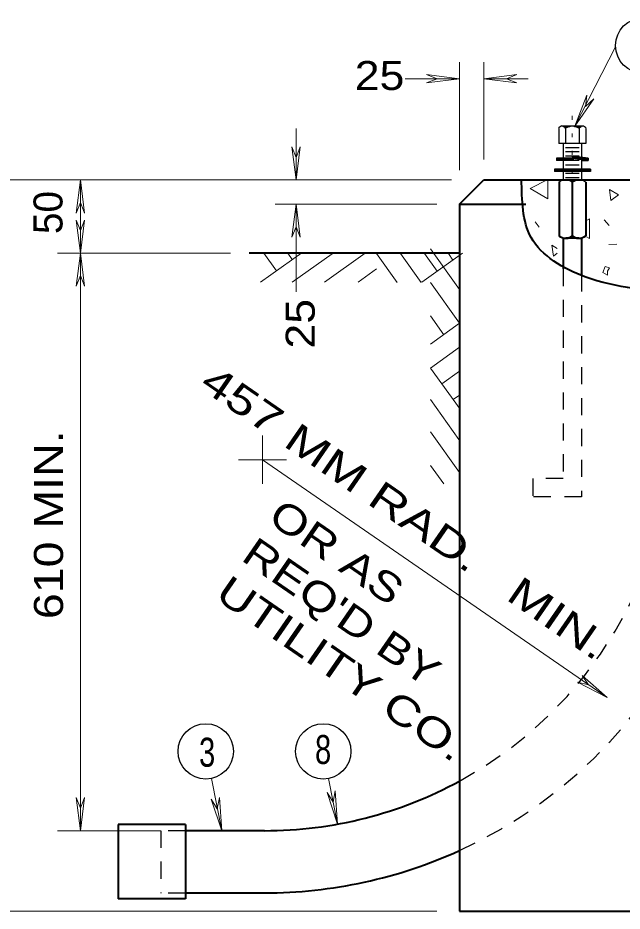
# Model space of a CAD drawing. Extents: x 312583 to 312854, y 144419 to 144597.
# Drawn here: x 312722.32 to 312738.15, y 144438.03 to 144461.45 of the extents above; entities that cross this region are included whole.
import ezdxf

# ---------------------------------------------------------------- set-up
doc = ezdxf.new("R2010")
doc.units = 0
doc.header["$LTSCALE"] = 0.3
doc.linetypes.add('DOTTED', pattern=[1.5, 0.3, -1.2])
doc.linetypes.add('SHORT_DASHED', pattern=[2.7, 1.5, -1.2])
doc.layers.add('1', color=7, linetype='Continuous', lineweight=25)
doc.layers.add('2', color=7, linetype='Continuous', lineweight=13)

msp = doc.modelspace()

# ---------------------------------------------------------------- linework, layer by layer
at = {"layer": '1', "linetype": 'DOTTED', "lineweight": 13}
msp.add_line((312736.843, 144458.8804), (312736.843, 144457.2014), dxfattribs=at)
at = {"layer": '1'}
for p, q in [((312737.1113, 144458.6044), (312736.5746, 144458.6197)), ((312736.4903, 144458.5507), (312736.4903, 144458.1597)), ((312736.6666, 144458.5507), (312736.6666, 144458.1597)), ((312737.027, 144458.5507), (312737.027, 144458.1597)), ((312737.2033, 144458.5507), (312737.2033, 144458.1597)), ((312737.2033, 144458.1597), (312736.4903, 144458.1597)), ((312736.6053, 144458.1597), (312736.6053, 144457.2014)), ((312737.0883, 144458.1597), (312737.0883, 144457.2014)), ((312737.027, 144458.0447), (312736.6666, 144458.0447)), ((312737.027, 144457.9374), (312736.6666, 144457.9374)), ((312736.429, 144457.7687), (312736.429, 144457.7074)), ((312736.866, 144457.7687), (312736.429, 144457.7687)), ((312736.8813, 144457.7074), (312736.429, 144457.7074)), ((312737.027, 144457.8224), (312736.6666, 144457.8224)), ((312737.027, 144457.7074), (312736.6666, 144457.7074)), ((312737.257, 144457.7687), (312737.257, 144457.7074)), ((312737.3183, 144457.485), (312736.3753, 144457.485)), ((312736.3753, 144457.485), (312736.3753, 144457.4237)), ((312737.3183, 144457.4697), (312736.3753, 144457.4697)), ((312737.3183, 144457.4544), (312736.3753, 144457.4544)), ((312737.3183, 144457.439), (312736.3753, 144457.439)), ((312737.027, 144457.5924), (312736.6666, 144457.5924)), ((312737.3183, 144457.485), (312737.3183, 144457.4237)), ((312737.3183, 144457.4237), (312736.3753, 144457.4237)), ((312737.0883, 144457.2014), (312736.6053, 144457.2014)), ((312737.027, 144457.37), (312736.6666, 144457.37)), ((312737.027, 144457.255), (312736.6666, 144457.255)), ((312737.0193, 144457.2014), (312736.6743, 144457.2014))]:
    msp.add_line(p, q, dxfattribs=at)
at = {"layer": '1', "lineweight": 40}
for p, q in [((312733.8913, 144456.565), (312734.5276, 144457.2014)), ((312734.5276, 144457.2014), (312777.9746, 144457.2014)), ((312736.843, 144457.2014), (312736.843, 144455.6757)), ((312736.498, 144457.14), (312736.498, 144455.737)), ((312737.1956, 144457.14), (312737.1956, 144455.737)), ((312733.8913, 144456.565), (312733.8913, 144438.0347)), ((312733.8913, 144456.565), (312735.624, 144456.565)), ((312736.6053, 144455.6757), (312736.6053, 144454.8707)), ((312737.0193, 144455.6757), (312736.6743, 144455.6757)), ((312737.0883, 144455.6757), (312737.0883, 144454.725)), ((312733.8913, 144455.2847), (312728.379, 144455.2847)), ((312726.7076, 144440.304), (312724.9443, 144440.304)), ((312724.9443, 144440.304), (312724.9443, 144438.3567)), ((312726.7076, 144440.304), (312726.7076, 144438.3567)), ((312728.7776, 144440.143), (312726.7076, 144440.143)), ((312728.7776, 144438.51), (312726.7076, 144438.51)), ((312726.7076, 144438.3567), (312724.9443, 144438.3567)), ((312733.8913, 144438.0347), (312778.611, 144438.0347))]:
    msp.add_line(p, q, dxfattribs=at)
at = {"layer": '1', "linetype": 'SHORT_DASHED'}
for p, q in [((312736.6053, 144454.8707), (312736.6053, 144449.3737)), ((312737.0883, 144454.725), (312737.0883, 144448.8984)), ((312737.0883, 144448.8984), (312735.808, 144448.8984)), ((312726.0636, 144440.143), (312726.0636, 144438.51)), ((312726.7076, 144440.143), (312726.0636, 144440.143)), ((312726.7076, 144438.51), (312726.0636, 144438.51))]:
    msp.add_line(p, q, dxfattribs=at)
at = {"layer": '1'}
for points in [[(312736.5976, 144458.612), (312736.797, 144458.612), (312736.7663, 144458.6044), (312736.7433, 144458.5967), (312736.705, 144458.5814), (312736.6666, 144458.5584), (312736.6513, 144458.5814), (312736.636, 144458.589), (312736.6053, 144458.6044), (312736.7816, 144458.6044), (312736.7356, 144458.5967), (312736.6973, 144458.5814), (312736.6666, 144458.566), (312736.6436, 144458.589), (312736.6206, 144458.6044), (312736.7586, 144458.6044), (312736.7126, 144458.589), (312736.6666, 144458.566), (312736.6283, 144458.6044), (312736.7433, 144458.6044), (312736.6666, 144458.5737), (312736.636, 144458.5967), (312736.7356, 144458.6044), (312736.6666, 144458.5737), (312736.6436, 144458.5967), (312736.7203, 144458.5967), (312736.6666, 144458.5814), (312736.6513, 144458.5967), (312736.6973, 144458.5967), (312736.6666, 144458.5814), (312736.659, 144458.5967), (312736.682, 144458.589), (312736.6666, 144458.589)], [(312737.0883, 144458.612), (312736.889, 144458.612), (312736.9273, 144458.6044), (312736.9503, 144458.5967), (312736.9886, 144458.5814), (312737.027, 144458.5584), (312737.0346, 144458.5814), (312737.0576, 144458.589), (312737.0806, 144458.6044), (312736.9043, 144458.6044), (312736.958, 144458.5967), (312736.9963, 144458.5814), (312737.0193, 144458.566), (312737.05, 144458.589), (312737.073, 144458.6044), (312736.9273, 144458.6044), (312736.981, 144458.589), (312737.0193, 144458.566), (312737.0576, 144458.6044), (312736.9426, 144458.6044), (312737.027, 144458.5737), (312737.0576, 144458.5967), (312736.958, 144458.6044), (312737.027, 144458.5737), (312737.05, 144458.5967), (312736.9733, 144458.5967), (312737.027, 144458.5814), (312737.0346, 144458.5967), (312736.9886, 144458.5967), (312737.0193, 144458.5814), (312737.027, 144458.5967), (312737.0116, 144458.589), (312737.0193, 144458.589)], [(312736.8736, 144457.715), (312736.4366, 144457.715), (312736.4366, 144457.761), (312736.8583, 144457.7534), (312736.8736, 144457.7227), (312736.4443, 144457.7227), (312736.4443, 144457.7534), (312736.8506, 144457.7457), (312736.8583, 144457.7304), (312736.452, 144457.7304), (312736.4596, 144457.738), (312736.4596, 144457.7457), (312736.8506, 144457.7457), (312736.8506, 144457.738), (312736.4596, 144457.738)], [(312737.257, 144457.7687), (312736.843, 144457.8224), (312736.8813, 144457.7074)], [(312737.0883, 144457.7074), (312737.257, 144457.715), (312737.2493, 144457.761), (312736.8583, 144457.8147), (312736.8736, 144457.7687), (312737.0883, 144457.738), (312737.0883, 144457.715), (312737.2493, 144457.7227), (312737.2493, 144457.7534), (312736.866, 144457.807), (312736.8736, 144457.7764), (312737.096, 144457.738), (312737.1036, 144457.7227), (312737.2416, 144457.7304), (312737.2416, 144457.7457), (312736.8813, 144457.7994), (312736.8813, 144457.784), (312737.096, 144457.7457), (312737.1113, 144457.738), (312737.1496, 144457.7304), (312737.234, 144457.738), (312736.889, 144457.7917), (312737.1803, 144457.738)], [(312736.866, 144457.7687), (312737.257, 144457.7074), (312737.0883, 144457.7074)], [(312736.9733, 144457.2014), (312736.7126, 144457.2014), (312736.7433, 144457.1937), (312736.774, 144457.186), (312736.8046, 144457.1707), (312736.82, 144457.163), (312736.843, 144457.1477), (312736.843, 144457.14), (312736.8966, 144457.1707), (312736.935, 144457.1937), (312736.958, 144457.1937), (312736.7356, 144457.2014), (312736.751, 144457.1937), (312736.774, 144457.1937), (312736.797, 144457.1784), (312736.8276, 144457.163), (312736.8353, 144457.1554), (312736.843, 144457.1477), (312736.889, 144457.1784), (312736.935, 144457.1937), (312736.7663, 144457.1937), (312736.8046, 144457.1784), (312736.843, 144457.1554), (312736.9196, 144457.1937), (312736.7816, 144457.1937), (312736.843, 144457.1554), (312736.9043, 144457.186), (312736.797, 144457.1937), (312736.843, 144457.163), (312736.8813, 144457.186), (312736.8123, 144457.186), (312736.843, 144457.1784), (312736.8813, 144457.1784), (312736.8583, 144457.1707), (312736.8506, 144457.186), (312736.8506, 144457.163), (312736.8353, 144457.1784), (312736.82, 144457.1784), (312736.8123, 144457.186)]]:
    msp.add_lwpolyline(points, dxfattribs=at)
at = {"layer": '1', "lineweight": 40}
msp.add_lwpolyline([(312736.9733, 144455.6757), (312736.7126, 144455.6757), (312736.7433, 144455.6834), (312736.774, 144455.691), (312736.8046, 144455.6987), (312736.82, 144455.714), (312736.843, 144455.7294), (312736.843, 144455.7294), (312736.8966, 144455.6987), (312736.935, 144455.6834), (312736.958, 144455.6757), (312736.7356, 144455.6757), (312736.751, 144455.6834), (312736.774, 144455.6834), (312736.797, 144455.691), (312736.8276, 144455.7064), (312736.8353, 144455.7217), (312736.843, 144455.7294), (312736.889, 144455.6987), (312736.935, 144455.6834), (312736.7663, 144455.6834), (312736.8046, 144455.691), (312736.843, 144455.7217), (312736.9196, 144455.6834), (312736.7816, 144455.6834), (312736.843, 144455.7217), (312736.9043, 144455.6834), (312736.797, 144455.6834), (312736.843, 144455.714), (312736.8813, 144455.691), (312736.8123, 144455.691), (312736.843, 144455.6987), (312736.8813, 144455.691), (312736.8583, 144455.7064), (312736.8506, 144455.691), (312736.8506, 144455.714), (312736.8353, 144455.6987), (312736.82, 144455.6987), (312736.8123, 144455.691)], dxfattribs=at)
at = {"layer": '1', "linetype": 'SHORT_DASHED'}
msp.add_lwpolyline([(312736.6053, 144449.3737), (312735.808, 144449.3737), (312735.808, 144448.8984)], dxfattribs=at)
at = {"layer": '1'}
for centre, radius, start, end in [((312736.5769, 144458.5118), 0.0993, 25.60064, 154.39936), ((312736.8455, 144458.2985), 0.3126, 55.04559, 124.95441), ((312737.1142, 144458.5118), 0.0993, 25.60064, 154.39936), ((312736.6708, 144456.9293), 0.272, 50.00693, 129.99306), ((312737.0203, 144456.9293), 0.272, 50.00694, 129.99307)]:
    msp.add_arc(centre, radius, start, end, dxfattribs=at)
at = {"layer": '1', "lineweight": 40}
for centre, radius, start, end in [((312736.6708, 144455.9466), 0.272, 230.00694, 309.99307), ((312737.0203, 144455.9466), 0.272, 230.00693, 309.99306), ((312728.7802, 144450.8285), 10.6854, 270, 298.57612), ((312728.7802, 144450.8285), 12.3146, 270, 294.52218)]:
    msp.add_arc(centre, radius, start, end, dxfattribs=at)
at = {"layer": '1', "linetype": 'SHORT_DASHED'}
for radius, start, end in [(10.6854, 298.57612, 0), (12.3146, 294.52268, 340.05203)]:
    msp.add_arc((312728.7802, 144450.8285), radius, start, end, dxfattribs=at)
at = {"layer": '1', "lineweight": 40}
msp.add_spline([(312749.332, 144453.9354), (312745.9203, 144453.7974), (312742.3246, 144453.8357), (312739.7256, 144454.2037), (312737.1726, 144454.6637), (312735.7696, 144455.691), (312735.5166, 144457.2167)], degree=3, dxfattribs=at)
at = {"layer": '2'}
for p, q in [((312737.9776, 144460.6897), (312736.912, 144458.612)), ((312733.8913, 144457.462), (312733.8913, 144460.291)), ((312734.5276, 144457.738), (312734.5276, 144460.291)), ((312732.4642, 144459.854), (312733.8913, 144459.854)), ((312733.025, 144459.9614), (312733.301, 144459.854)), ((312733.8913, 144459.854), (312733.025, 144459.9614)), ((312733.025, 144459.7467), (312733.301, 144459.854)), ((312733.8913, 144459.854), (312733.025, 144459.7467)), ((312734.5276, 144459.854), (312735.394, 144459.9614)), ((312734.5276, 144459.854), (312735.6853, 144459.854)), ((312734.5276, 144459.854), (312735.394, 144459.7467)), ((312735.394, 144459.9614), (312735.118, 144459.854)), ((312735.394, 144459.7467), (312735.118, 144459.854)), ((312736.912, 144458.612), (312737.2263, 144459.4247)), ((312736.912, 144458.612), (312737.4103, 144459.325)), ((312737.2263, 144459.4247), (312737.188, 144459.1257)), ((312737.4103, 144459.325), (312737.188, 144459.1257)), ((312729.6056, 144457.2014), (312729.6056, 144458.5507)), ((312729.4983, 144458.0677), (312729.6056, 144457.7917)), ((312729.6056, 144457.2014), (312729.4983, 144458.0677)), ((312729.713, 144458.0677), (312729.6056, 144457.7917)), ((312729.6056, 144457.2014), (312729.713, 144458.0677)), ((312733.6766, 144457.2014), (312720.4823, 144457.2014)), ((312723.9553, 144457.2014), (312723.848, 144456.335)), ((312723.9553, 144457.2014), (312724.0626, 144456.335)), ((312723.848, 144456.335), (312723.9553, 144456.611)), ((312724.0626, 144456.335), (312723.9553, 144456.611)), ((312733.2933, 144456.565), (312729.0613, 144456.565)), ((312729.6056, 144456.565), (312729.4983, 144455.6987)), ((312729.6056, 144454.265), (312729.6056, 144456.565)), ((312729.6056, 144456.565), (312729.713, 144455.6987)), ((312723.848, 144456.151), (312723.9553, 144455.875)), ((312723.9553, 144455.2847), (312723.848, 144456.151)), ((312724.0626, 144456.151), (312723.9553, 144455.875)), ((312723.9553, 144455.2847), (312724.0626, 144456.151)), ((312735.8693, 144456.105), (312735.9766, 144455.967)), ((312737.6786, 144456.1587), (312737.809, 144456.0054)), ((312729.4983, 144455.6987), (312729.6056, 144455.9747)), ((312729.713, 144455.6987), (312729.6056, 144455.9747)), ((312737.1956, 144455.7217), (312737.2953, 144455.668)), ((312733.1323, 144455.392), (312733.8913, 144454.3264)), ((312737.8013, 144455.507), (312738.0083, 144455.5224)), ((312727.8883, 144455.2847), (312723.3573, 144455.2847)), ((312723.9553, 144455.2847), (312723.848, 144454.4184)), ((312723.9553, 144455.2847), (312724.0626, 144454.4184)), ((312728.678, 144454.5257), (312729.759, 144455.2924)), ((312728.7623, 144455.2847), (312729.092, 144454.817)), ((312729.391, 144455.2847), (312729.506, 144455.116)), ((312729.506, 144454.5257), (312730.5486, 144455.2617)), ((312730.3493, 144454.5257), (312731.415, 144455.2847)), ((312731.714, 144455.2694), (312732.2583, 144454.5104)), ((312732.3426, 144455.2694), (312732.887, 144454.5104)), ((312732.9023, 144454.5257), (312733.968, 144455.2847)), ((312732.9713, 144455.2694), (312733.301, 144454.8094)), ((312733.6, 144455.2694), (312733.715, 144455.1007)), ((312736.3523, 144455.2004), (312736.452, 144455.2847)), ((312731.231, 144454.5257), (312731.714, 144454.8707)), ((312723.848, 144454.4184), (312723.9553, 144454.6944)), ((312724.0626, 144454.4184), (312723.9553, 144454.6944)), ((312733.1323, 144454.5104), (312733.8913, 144453.4447)), ((312733.1323, 144453.6364), (312733.4773, 144453.1457)), ((312733.8913, 144453.4447), (312733.1323, 144452.9004)), ((312733.8913, 144452.816), (312733.1323, 144452.2717)), ((312733.1323, 144452.2717), (312733.9066, 144451.1907)), ((312733.8913, 144452.1874), (312733.4236, 144451.8577)), ((312733.1323, 144451.4437), (312733.8683, 144450.401)), ((312733.8913, 144451.5587), (312733.7226, 144451.4437)), ((312728.7316, 144449.8644), (312728.7316, 144450.5007)), ((312733.1323, 144450.6004), (312733.8913, 144449.5347)), ((312728.7316, 144449.8644), (312728.0953, 144449.8644)), ((312728.7316, 144449.8644), (312737.7553, 144443.639)), ((312728.7316, 144449.8644), (312729.3603, 144449.8644)), ((312728.7316, 144449.8644), (312728.7316, 144449.2357)), ((312733.1323, 144449.7187), (312733.4773, 144449.2357)), ((312737.1036, 144444.214), (312737.2723, 144443.9687)), ((312737.7553, 144443.639), (312737.1036, 144444.214)), ((312736.981, 144444.0377), (312737.2723, 144443.9687)), ((312737.7553, 144443.639), (312736.981, 144444.0377)), ((312727.39, 144441.5077), (312727.666, 144440.143)), ((312730.4566, 144441.5077), (312730.6943, 144440.3117)), ((312730.4183, 144441.1474), (312730.5793, 144440.8944)), ((312730.6943, 144440.3117), (312730.4183, 144441.1474)), ((312730.633, 144441.1857), (312730.5793, 144440.8944)), ((312730.6943, 144440.3117), (312730.633, 144441.1857)), ((312723.848, 144441.0094), (312723.9553, 144440.7334)), ((312723.9553, 144440.143), (312723.848, 144441.0094)), ((312724.0626, 144441.0094), (312723.9553, 144440.7334)), ((312723.9553, 144440.143), (312724.0626, 144441.0094)), ((312727.3823, 144440.971), (312727.5433, 144440.718)), ((312727.666, 144440.143), (312727.3823, 144440.971)), ((312727.597, 144441.0094), (312727.5433, 144440.718)), ((312727.666, 144440.143), (312727.597, 144441.0094)), ((312726.0636, 144440.143), (312723.3573, 144440.143)), ((312733.2933, 144438.0347), (312720.4823, 144438.0347))]:
    msp.add_line(p, q, dxfattribs=at)
for points in [[(312723.9553, 144440.143), (312723.9553, 144455.2847), (312723.9553, 144457.2014)], [(312737.2953, 144455.668), (312737.2953, 144456.1817), (312737.1956, 144456.128)], [(312736.452, 144455.4074), (312736.3063, 144455.4917), (312736.3523, 144455.2004)]]:
    msp.add_lwpolyline(points, dxfattribs=at)
for points in [[(312736.2066, 144456.703), (312736.2066, 144457.2167), (312735.739, 144456.979)], [(312737.855, 144456.6647), (312738.0543, 144456.8104), (312737.8166, 144456.9484)], [(312737.7706, 144454.8094), (312737.8166, 144454.8937), (312737.7016, 144454.932), (312737.6403, 144454.7787), (312737.7706, 144454.7097)]]:
    msp.add_lwpolyline(points, close=True, dxfattribs=at)
at = {"layer": '2', "lineweight": 25}
for centre in [(312738.7021, 144460.7248), (312727.2417, 144442.2226), (312730.3193, 144442.2226)]:
    msp.add_circle(centre, 0.7254, dxfattribs=at)

# ---------------------------------------------------------------- texts
at = {"layer": '2'}
for s, width, p in [('25 ', 1.15, (312731.1444, 144459.5593)), ('3', 0.75, (312727.0648, 144441.8202)), ('8', 0.75, (312730.1033, 144441.8921))]:
    msp.add_text(s, height=0.76, dxfattribs=dict(at, width=width)).set_placement(p)
msp.add_text('50', height=0.76, rotation=90, dxfattribs=at).set_placement((312723.4873, 144455.7825))
for s, rotation, width, p in [('25 ', 90, 1.15, (312730.096, 144452.7818)), ('457 MM RAD.   MIN.', 325.387, 1.35, (312727.0453, 144451.7654)), ('610 MIN.', 90, 1.2, (312723.501, 144445.6886)), ('OR AS', 325.4, 1.25, (312728.829, 144448.2569)), ("REQ'D BY", 325.4, 1.25, (312728.1362, 144447.2526)), ('UTILITY CO.', 325.4, 1.3, (312727.4434, 144446.2484))]:
    msp.add_text(s, height=0.76, rotation=rotation, dxfattribs=dict(at, width=width)).set_placement(p)

doc.saveas('drawing.dxf')
